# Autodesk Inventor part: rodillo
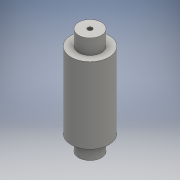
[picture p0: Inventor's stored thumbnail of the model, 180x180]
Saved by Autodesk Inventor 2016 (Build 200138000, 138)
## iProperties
Created: 2016-06
Part Number: rodillo
Material: Generic
Document SubType Name: Modeling
Designer: yesi alvarez
Mass: 27.9366 g
Surface Area: 60.3971 cm^2
Volume: 27.9366 cm^3
Density: 1 g/cm^3
Appearance: Default
Author: yesi alvarez
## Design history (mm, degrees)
sketch "Sketch1"
  geometry: C1 r 12.5 at (0, 0); 1 further point
  constraints: 1 centre point, 1 coincident
  dimensions: "d0" = 25 diameter of C1
extrude "Extrusion1" new body sketch "Sketch1" distance "d1" = 25; taper "d2" = 0 deg
sketch "Sketch2"
  geometry: C1 r 7.5 at (0, 0); 1 further point
  constraints: 1 centre point, 1 coincident
  dimensions: "d3" = 15 diameter of C1
extrude "Extrusion2" join sketch "Sketch2" distance "d4" = 10; taper "d5" = 0 deg
sketch "Sketch3"
  geometry: C1 r 1.5 at (0, 0); 1 further point
  constraints: 1 centre point, 1 coincident
  dimensions: "d6" = 3 diameter of C1
extrude "Extrusion3" cut sketch "Sketch3" distance "d7" = 10; taper "d8" = 0 deg
thread "Thread1" dims "d9" = 10, "d10" = 0
mirror "Mirror1"
node "Hole2"
body "Solid1"
sketch "Sketch4"
  geometry: 1 further point
hole "Hole1" sketch "Sketch4" diameter "d11" = 2.459; stored, may be unused: countersink angle "d15" = 90 deg, drill point angle "d17" = 120 deg; dims "d12" = 3, "d13" = 4, "d14" = 2, "d16" = 4.5
